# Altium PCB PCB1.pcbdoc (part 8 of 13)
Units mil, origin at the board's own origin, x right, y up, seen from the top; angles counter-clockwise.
Board outline 5895.51 x 5895.51 mil, 8 copper layers (Top Layer, L2_GND1, L3_SIG1, L4_GND2, L5_PWR, L6_SIG2, L7_GND3, Bottom Layer), stack 63.761 mil thick; 673 components, 558 nets, 2797 pads, 1861 vias.
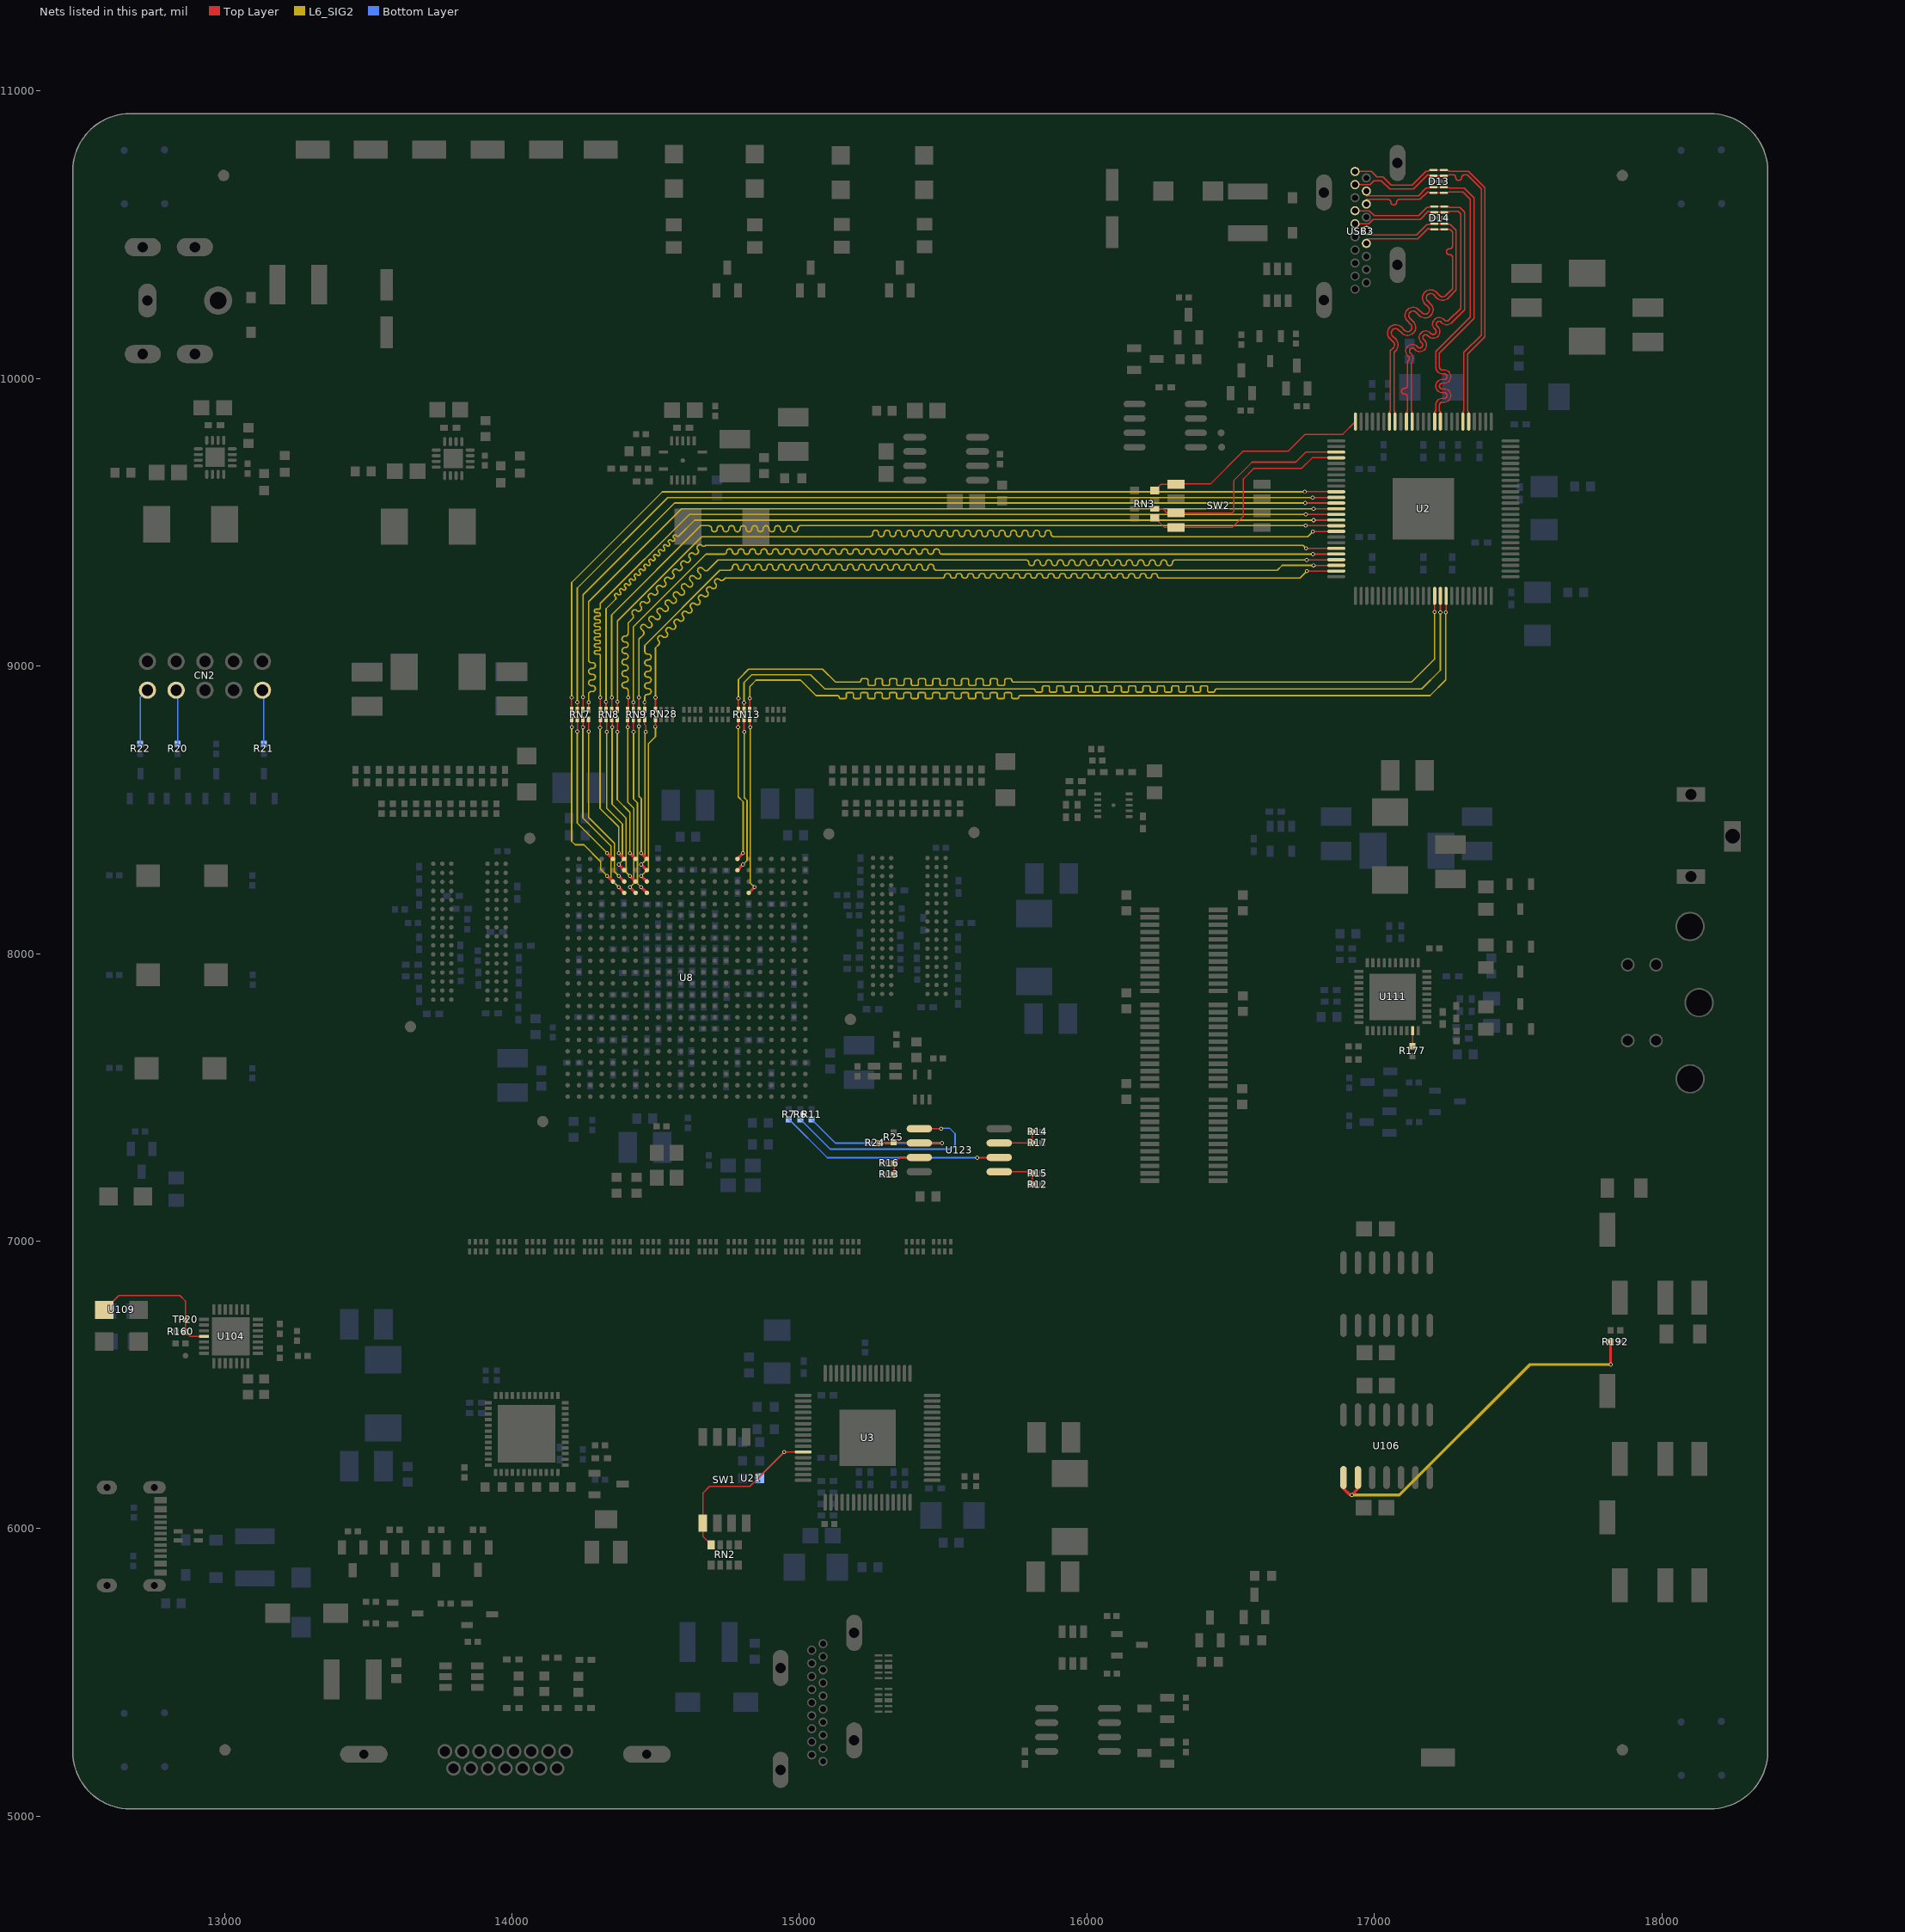
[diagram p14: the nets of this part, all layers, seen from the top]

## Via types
v1: diameter 23.62, hole 15.75, Top Layer to Bottom Layer, 621 vias
v2: diameter 13.8, hole 7.9, Top Layer to Bottom Layer, 567 vias
v3: diameter 13.78, hole 7.87, Top Layer to Bottom Layer, 529 vias
v4: diameter 13.78, hole 7.9, Top Layer to Bottom Layer, 114 vias
v5: diameter 15.75, hole 7.87, Top Layer to Bottom Layer, 16 vias
v6: diameter 24, hole 12, Top Layer to Bottom Layer, 10 vias
v7: diameter 11.81, hole 7.87, Top Layer to Bottom Layer, 4 vias

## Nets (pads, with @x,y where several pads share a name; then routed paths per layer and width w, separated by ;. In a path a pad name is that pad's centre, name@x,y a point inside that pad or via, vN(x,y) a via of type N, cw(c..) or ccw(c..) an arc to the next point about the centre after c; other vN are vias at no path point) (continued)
MIC2_OR: R192.1 U106.8 U106.9 | length 1314.7
  Top Layer w10: U106.8@16892.36,6177.98 16892.36,6140 16915.36,6117 v4(16921.36,6117) 16940.36,6136 16940.36,6175.98 U106.9@16942.36,6177.98 ; R192.1@17821.32,6650 17821.32,6572.04 v3(17822.36,6571)
  L6_SIG2 w10: v4(16921.36,6117) 17086.36,6117 17540.36,6571 v3(17822.36,6571)
  other v3: 17822.36,6571
MSEN: RN2.8 SW1.1 U3.11 U21.2 | length 725.3
  Top Layer w4.7: RN2.8@14693.12,5944.44 14664.36,5973.19 SW1.1@14664.36,6019 14664.36,6124 14687.36,6147 14827.36,6147 v4(14947.15,6266.79) U3.11@15012.95,6266.79
  Bottom Layer w4.7: U21.2@14862.02,6176 14862.02,6181.66 v4(14947.15,6266.79)
OCK_INV: RN3.8 SW2.1 U2.100 | length 797.5
  Top Layer w4.7: RN3.8@16236.01,9610.24 16257.77,9632 SW2.1@16309.36,9632 16310.36,9633 16429.36,9633 16543.36,9747 16700.36,9747 16759.36,9806 16889.99,9806 U2.100@16934.14,9850.15
PIXS: RN3.5 SW2.4 U2.4 | length 821.6
  Top Layer w4.7: RN3.5@16236.01,9515.76 16269.77,9482 SW2.4@16309.36,9482 16505.36,9482 16544.36,9521 16544.36,9651 16580.36,9687 16746.36,9687 16783.52,9724.16 U2.4@16867.21,9724.16
QSPI_CCLK: R11.1 R24.1 R25.2 U123.6 | length 705.8
  Top Layer w4.7: R24.1@15279.4,7341 15324.4,7341 R25.2@15327.36,7343.96 15330.06,7341.26 U123.6@15417.2,7341.26 15417.46,7341 v3(15495.36,7341)
  Bottom Layer w4.7: R11.1@15042.36,7423.96 15125.32,7341 v3(15495.36,7341)
QSPI_CS: R12.1 R15.1 U123.1 | length 156.3
  Top Layer w4.7: U123.1@15695.16,7241.26 15805.06,7241.26 R15.1@15810.32,7236 R12.1@15810.32,7197
QSPI_DIN: R7.1 U123.2 | length 787.8
  Top Layer w4.7: v3(15618.36,7290) 15693.91,7290 U123.2@15695.16,7291.26
  Bottom Layer w4.7: R7.1@14963.36,7423.96 15097.32,7290 v3(15618.36,7290)
QSPI_HOLD: R13.1 R16.1 U123.7 | length 135.2
  Top Layer w4.7: R13.1@15329.4,7232 R16.1@15329.4,7271 15349.65,7291.26 U123.7@15417.2,7291.26
QSPI_OUT: R6.1 U123.5 | length 759
  Top Layer w4.7: U123.5@15417.2,7391.26 15417.46,7391 v3(15493.36,7391)
  Bottom Layer w4.7: R6.1@15003.36,7423.96 15107.32,7320 15527.36,7320 15541.36,7334 15541.36,7374 15523.36,7392 15494.36,7392 v3(15493.36,7391)
QSPI_WP: R14.1 R17.1 U123.3 | length 154.1
  Top Layer w4.7: U123.3@15695.16,7341.26 R17.1@15810.06,7341.26 ; R17.1@15810.32,7341 R17.1@15810.06,7341.26 ; R14.1@15810.32,7380 15810.32,7341.51 R17.1@15810.06,7341.26
RXD: R160.1 TP20.1 U104.25 U109.1 | length 488.6
  Top Layer w4.7: U109.1@12582.62,6761 12632.62,6811 12845.36,6811 12864.07,6792.29 TP20.1@12864.07,6726.85 12864.73,6726.19 R160.1@12864.73,6684.8 12880.62,6668.91 U104.25@12929.09,6668.91
ST: RN3.6 SW2.3 U2.3 | length 788.5
  Top Layer w4.7: RN3.6@16236.01,9547.25 16264.11,9547.25 16279.36,9532 SW2.3@16309.36,9532 16505.36,9532 16510.36,9537 16510.36,9645 16574.36,9709 16726.36,9709 16761.21,9743.85 U2.3@16867.21,9743.85
SVIDEO_CLKIN_27M: R177.2 U111.19 | length 53.2
  Top Layer w4.7: R177.2@17132.36,7678.04 17132.56,7678.24 U111.19@17132.56,7731.16
TCK: CN2.1 R22.1 | length 197
  Bottom Layer w4.7: R22.1@12707.36,8729.37 12707.36,8891 CN2.1@12732.36,8916
TDI: CN2.9 R21.1 | length 188.7
  Bottom Layer w4.7: CN2.9@13132.36,8916 13137.36,8911 R21.1@13137.36,8729.37
TDO: CN2.3 R20.1 | length 188.7
  Bottom Layer w4.7: CN2.3@12832.36,8916 12837.36,8911 R20.1@12837.36,8729.37
TFP401_C+: D14.4 D14.7 U2.93 USB3.10 | length 1353.3
  Top Layer w4: USB3.10@16972.04,10515.22 16972.04,10500.38 16973.46,10498.97 17145.92,10498.97 17181.92,10534.97 17189.31,10534.97 17192.64,10538.3 D14.4@17208.03,10538.3 17240.13,10538.3 D14.7@17241.56,10536.87 ; U2.93@17071.93,9850.15 17071.93,9883.65 17068.59,9886.99 17068.59,10091.23 17074.38,10097.03 ccw(c17054.58,10116.83) 17074.38,10136.63 17062.95,10148.06 cw(c17073.56,10158.66) 17084.16,10169.27 17095.59,10157.84 ccw(c17115.39,10177.64) 17135.19,10197.44 17123.76,10208.87 cw(c17134.37,10219.47) 17144.97,10230.08 17156.4,10218.65 ccw(c17176.2,10238.45) 17196,10258.25 17184.57,10269.68 cw(c17195.18,10280.28) 17205.78,10290.89 17217.22,10279.46 ccw(c17237.01,10299.26) 17256.81,10279.46 17284.4,10307.05 17284.4,10515.28 17262.8,10536.89 17244.1,10536.89 D14.7@17242.69,10538.3
TFP401_C-: D14.5 D14.6 U2.94 USB3.12 | length 1351.7
  Top Layer w4: USB3.12@16972.04,10469.71 16972.04,10484.55 16973.46,10485.97 17151.31,10485.97 17187.31,10521.97 17189.31,10521.97 17192.64,10518.63 D14.5@17208.04,10518.63 17239.81,10518.63 D14.6@17240.41,10518.03 ; U2.94@17052.25,9850.15 17052.25,9883.65 17055.59,9886.99 17055.59,10096.62 17065.19,10106.22 ccw(c17054.58,10116.83) 17065.19,10127.43 17053.76,10138.86 cw(c17073.56,10158.66) 17093.35,10178.46 17104.79,10167.03 ccw(c17115.39,10177.64) 17126,10188.24 17114.57,10199.67 cw(c17134.37,10219.47) 17154.17,10239.27 17165.6,10227.84 ccw(c17176.2,10238.45) 17186.81,10249.06 17175.38,10260.49 cw(c17195.18,10280.28) 17214.98,10300.08 17226.41,10288.65 ccw(c17237.01,10299.26) 17247.62,10288.65 17271.4,10312.44 17271.4,10420.77 ccw(c17261.4,10420.77) 17261.4,10430.77 17260.79,10430.77 cw(c17260.79,10440.77) 17260.79,10450.77 17261.4,10450.77 ccw(c17261.4,10460.77) 17271.4,10460.77 17271.4,10509.9 17263.31,10517.99 17242.95,10517.99 17242.69,10518.26 D14.6@17242.69,10518.63
TFP401_CTL1: RN13.5 U2.40 | length 3206
  Top Layer w4.7: RN13.5@14787.83,8847.83 v3(14787.83,8887) ; U2.40@17208.87,9244.88 17209.36,9244.4 v4(17209.36,9188)
  L6_SIG2 w5: v3(14787.83,8887) 14787.83,8953.47 14823.46,8989.1 15080.67,8989.1 15125.71,8944.07 15207.93,8944.07 ccw(c15207.93,8950.08) 15213.94,8950.08 cw(c15219.95,8950.08) 15219.95,8956.09 15232.93,8956.09 cw(c15232.93,8950.08) 15238.94,8950.08 15238.94,8938.06 ccw(c15244.95,8938.06) 15244.95,8932.05 15257.93,8932.05 ccw(c15257.93,8938.06) 15263.94,8938.06 15263.94,8950.08 cw(c15269.95,8950.08) 15269.95,8956.09 15282.93,8956.09 cw(c15282.93,8950.08) 15288.94,8950.08 15288.94,8938.06 ccw(c15294.95,8938.06) 15294.95,8932.05 15307.93,8932.05 ccw(c15307.93,8938.06) 15313.94,8938.06 15313.94,8950.08 cw(c15319.95,8950.08) 15319.95,8956.09 15332.93,8956.09 cw(c15332.93,8950.08) 15338.94,8950.08 15338.94,8938.06 ccw(c15344.95,8938.06) 15344.95,8932.05 15357.93,8932.05 ccw(c15357.93,8938.06) 15363.94,8938.06 15363.94,8950.08 cw(c15369.95,8950.08) 15369.95,8956.09 15382.93,8956.09 cw(c15382.93,8950.08) 15388.94,8950.08 15388.94,8938.06 ccw(c15394.95,8938.06) 15394.95,8932.05 15407.93,8932.05 ccw(c15407.93,8938.06) 15413.94,8938.06 15413.94,8950.08 cw(c15419.95,8950.08) 15419.95,8956.09 15432.93,8956.09 cw(c15432.93,8950.08) 15438.94,8950.08 15438.94,8938.06 ccw(c15444.95,8938.06) 15444.95,8932.05 15457.93,8932.05 ccw(c15457.93,8938.06) 15463.94,8938.06 15463.94,8950.08 cw(c15469.95,8950.08) 15469.95,8956.09 15482.93,8956.09 cw(c15482.93,8950.08) 15488.94,8950.08 15488.94,8938.06 ccw(c15494.95,8938.06) 15494.95,8932.05 15507.93,8932.05 ccw(c15507.93,8938.06) 15513.94,8938.06 15513.94,8950.08 cw(c15519.95,8950.08) 15519.95,8956.09 15532.93,8956.09 cw(c15532.93,8950.08) 15538.94,8950.08 15538.94,8938.06 ccw(c15544.95,8938.06) 15544.95,8932.05 15557.93,8932.05 ccw(c15557.93,8938.06) 15563.94,8938.06 15563.94,8950.08 cw(c15569.95,8950.08) 15569.95,8956.09 15582.93,8956.09 cw(c15582.93,8950.08) 15588.94,8950.08 15588.94,8938.06 ccw(c15594.95,8938.06) 15594.95,8932.05 15607.93,8932.05 ccw(c15607.93,8938.06) 15613.94,8938.06 15613.94,8950.08 cw(c15619.95,8950.08) 15619.95,8956.09 15632.93,8956.09 cw(c15632.93,8950.08) 15638.94,8950.08 15638.94,8938.06 ccw(c15644.95,8938.06) 15644.95,8932.05 15657.93,8932.05 ccw(c15657.93,8938.06) 15663.94,8938.06 15663.94,8950.08 cw(c15669.95,8950.08) 15669.95,8956.09 15682.93,8956.09 cw(c15682.93,8950.08) 15688.94,8950.08 15688.94,8938.06 ccw(c15694.95,8938.06) 15694.95,8932.05 15707.93,8932.05 ccw(c15707.93,8938.06) 15713.94,8938.06 15713.94,8950.08 cw(c15719.95,8950.08) 15719.95,8956.09 15732.93,8956.09 cw(c15732.93,8950.08) 15738.94,8950.08 ccw(c15744.95,8950.08) 15744.95,8944.07 17128.96,8944.07 17209.62,9024.73 ; 17209.36,9024.73 v4(17209.36,9188)
TFP401_CTL1_FPGA: RN13.4 U8.A16 | length 500.7
  Top Layer w4.7: v3(14786.59,8786.88) 14787.83,8788.12 RN13.4@14787.83,8814.17
  Top Layer w10: U8.A16@14784.52,8329.4 v2(14804.2,8349.07)
  L6_SIG2 w5: v3(14786.59,8786.88) 14787.07,8786.41 14787.07,8545.09 14804.2,8527.96 v2(14804.2,8349.07)
TFP401_CTL2: RN13.6 U2.41 | length 3261.2
  Top Layer w4.7: v3(14807.36,8873) 14807.52,8872.84 RN13.6@14807.52,8847.83 ; v4(17229.36,9187) U2.41@17229.36,9243.95
  L6_SIG2 w5: v3(14807.36,8873) 14807.36,8943 14834.46,8970.1 15038.67,8970.1 15088.73,8920.04 15814.44,8920.04 cw(c15814.44,8914.55) 15819.93,8914.55 ccw(c15825.41,8914.55) 15825.41,8909.07 15839.44,8909.07 ccw(c15839.44,8914.55) 15844.93,8914.55 15844.93,8925.53 cw(c15850.41,8925.53) 15850.41,8931.01 15864.44,8931.01 cw(c15864.44,8925.53) 15869.93,8925.53 15869.93,8914.55 ccw(c15875.41,8914.55) 15875.41,8909.07 15889.44,8909.07 ccw(c15889.44,8914.55) 15894.93,8914.55 15894.93,8925.53 cw(c15900.41,8925.53) 15900.41,8931.01 15914.44,8931.01 cw(c15914.44,8925.53) 15919.93,8925.53 15919.93,8914.55 ccw(c15925.41,8914.55) 15925.41,8909.07 15939.44,8909.07 ccw(c15939.44,8914.55) 15944.93,8914.55 15944.93,8925.53 cw(c15950.41,8925.53) 15950.41,8931.01 15964.44,8931.01 cw(c15964.44,8925.53) 15969.93,8925.53 15969.93,8914.55 ccw(c15975.41,8914.55) 15975.41,8909.07 15989.44,8909.07 ccw(c15989.44,8914.55) 15994.93,8914.55 15994.93,8925.53 cw(c16000.41,8925.53) 16000.41,8931.01 16014.44,8931.01 cw(c16014.44,8925.53) 16019.93,8925.53 16019.93,8914.55 ccw(c16025.41,8914.55) 16025.41,8909.07 16039.44,8909.07 ccw(c16039.44,8914.55) 16044.93,8914.55 16044.93,8925.53 cw(c16050.41,8925.53) 16050.41,8931.01 16064.44,8931.01 cw(c16064.44,8925.53) 16069.93,8925.53 16069.93,8914.55 ccw(c16075.41,8914.55) 16075.41,8909.07 16089.44,8909.07 ccw(c16089.44,8914.55) 16094.93,8914.55 16094.93,8925.53 cw(c16100.41,8925.53) 16100.41,8931.01 16114.44,8931.01 cw(c16114.44,8925.53) 16119.93,8925.53 16119.93,8914.55 ccw(c16125.41,8914.55) 16125.41,8909.07 16139.44,8909.07 ccw(c16139.44,8914.55) 16144.93,8914.55 16144.93,8925.53 cw(c16150.41,8925.53) 16150.41,8931.01 16164.44,8931.01 cw(c16164.44,8925.53) 16169.93,8925.53 16169.93,8914.55 ccw(c16175.41,8914.55) 16175.41,8909.07 16189.44,8909.07 ccw(c16189.44,8914.55) 16194.93,8914.55 16194.93,8925.53 cw(c16200.41,8925.53) 16200.41,8931.01 16214.44,8931.01 cw(c16214.44,8925.53) 16219.93,8925.53 16219.93,8914.55 ccw(c16225.41,8914.55) 16225.41,8909.07 16239.44,8909.07 ccw(c16239.44,8914.55) 16244.93,8914.55 16244.93,8925.53 cw(c16250.41,8925.53) 16250.41,8931.01 16264.44,8931.01 cw(c16264.44,8925.53) 16269.93,8925.53 16269.93,8914.55 ccw(c16275.41,8914.55) 16275.41,8909.07 16289.44,8909.07 ccw(c16289.44,8914.55) 16294.93,8914.55 16294.93,8925.53 cw(c16300.41,8925.53) 16300.41,8931.01 16314.44,8931.01 cw(c16314.44,8925.53) 16319.93,8925.53 16319.93,8914.55 ccw(c16325.41,8914.55) 16325.41,8909.07 16339.44,8909.07 ccw(c16339.44,8914.55) 16344.93,8914.55 16344.93,8925.53 cw(c16350.41,8925.53) 16350.41,8931.01 16364.44,8931.01 cw(c16364.44,8925.53) 16369.93,8925.53 16369.93,8914.55 ccw(c16375.41,8914.55) 16375.41,8909.07 16389.44,8909.07 ccw(c16389.44,8914.55) 16394.93,8914.55 16394.93,8925.53 cw(c16400.41,8925.53) 16400.41,8931.01 16414.44,8931.01 cw(c16414.44,8925.53) 16419.93,8925.53 16419.93,8914.55 ccw(c16425.41,8914.55) 16425.41,8909.07 16439.44,8909.07 ccw(c16439.44,8914.55) 16444.93,8914.55 cw(c16450.41,8914.55) 16450.41,8920.04 17164.13,8920.04 17229.43,8985.34 ; 17229.36,8985.34 v4(17229.36,9187)
TFP401_CTL2_FPGA: RN13.3 U8.B16 | length 542.4
  Top Layer w4.7: RN13.3@14807.52,8814.17 14807.52,8770.96 v3(14807.8,8770.68)
  Top Layer w10: U8.B16@14784.52,8290.01 v2(14804.2,8309.69)
  L6_SIG2 w5: v2(14804.2,8309.69) 14818.07,8323.56 14818.07,8532.25 14807.8,8542.51 v3(14807.8,8770.68)
TFP401_CTL3: RN13.7 U2.42 | length 3247
  Top Layer w4.7: RN13.7@14827.2,8847.83 v3(14827.2,8887) ; v4(17248.36,9186) 17249.34,9186.98 U2.42@17249.34,9237
  L6_SIG2 w5: v3(14827.2,8887) 14827.2,8928.84 14849.46,8951.1 15003.81,8951.1 15057.72,8897.19 15132.84,8897.19 cw(c15132.84,8891.97) 15138.05,8891.97 ccw(c15143.27,8891.97) 15143.27,8886.76 15157.84,8886.76 ccw(c15157.84,8891.97) 15163.05,8891.97 15163.05,8902.41 cw(c15168.27,8902.41) 15168.27,8907.62 15182.84,8907.62 cw(c15182.84,8902.41) 15188.05,8902.41 15188.05,8891.97 ccw(c15193.27,8891.97) 15193.27,8886.76 15207.84,8886.76 ccw(c15207.84,8891.97) 15213.05,8891.97 15213.05,8902.41 cw(c15218.27,8902.41) 15218.27,8907.62 15232.84,8907.62 cw(c15232.84,8902.41) 15238.05,8902.41 15238.05,8891.97 ccw(c15243.27,8891.97) 15243.27,8886.76 15257.84,8886.76 ccw(c15257.84,8891.97) 15263.05,8891.97 15263.05,8902.41 cw(c15268.27,8902.41) 15268.27,8907.62 15282.84,8907.62 cw(c15282.84,8902.41) 15288.05,8902.41 15288.05,8891.97 ccw(c15293.27,8891.97) 15293.27,8886.76 15307.84,8886.76 ccw(c15307.84,8891.97) 15313.05,8891.97 15313.05,8902.41 cw(c15318.27,8902.41) 15318.27,8907.62 15332.84,8907.62 cw(c15332.84,8902.41) 15338.05,8902.41 15338.05,8891.97 ccw(c15343.27,8891.97) 15343.27,8886.76 15357.84,8886.76 ccw(c15357.84,8891.97) 15363.05,8891.97 15363.05,8902.41 cw(c15368.27,8902.41) 15368.27,8907.62 15382.84,8907.62 cw(c15382.84,8902.41) 15388.05,8902.41 15388.05,8891.97 ccw(c15393.27,8891.97) 15393.27,8886.76 15407.84,8886.76 ccw(c15407.84,8891.97) 15413.05,8891.97 15413.05,8902.41 cw(c15418.27,8902.41) 15418.27,8907.62 15432.84,8907.62 cw(c15432.84,8902.41) 15438.05,8902.41 15438.05,8891.97 ccw(c15443.27,8891.97) 15443.27,8886.76 15457.84,8886.76 ccw(c15457.84,8891.97) 15463.05,8891.97 15463.05,8902.41 cw(c15468.27,8902.41) 15468.27,8907.62 15482.84,8907.62 cw(c15482.84,8902.41) 15488.05,8902.41 15488.05,8891.97 ccw(c15493.27,8891.97) 15493.27,8886.76 15507.84,8886.76 ccw(c15507.84,8891.97) 15513.05,8891.97 15513.05,8902.41 cw(c15518.27,8902.41) 15518.27,8907.62 15532.84,8907.62 cw(c15532.84,8902.41) 15538.05,8902.41 15538.05,8891.97 ccw(c15543.27,8891.97) 15543.27,8886.76 15557.84,8886.76 ccw(c15557.84,8891.97) 15563.05,8891.97 15563.05,8902.41 cw(c15568.27,8902.41) 15568.27,8907.62 15582.84,8907.62 cw(c15582.84,8902.41) 15588.05,8902.41 15588.05,8891.97 ccw(c15593.27,8891.97) 15593.27,8886.76 15607.84,8886.76 ccw(c15607.84,8891.97) 15613.05,8891.97 15613.05,8902.41 cw(c15618.27,8902.41) 15618.27,8907.62 15632.84,8907.62 cw(c15632.84,8902.41) 15638.05,8902.41 15638.05,8891.97 ccw(c15643.27,8891.97) 15643.27,8886.76 15657.84,8886.76 ccw(c15657.84,8891.97) 15663.05,8891.97 15663.05,8902.41 cw(c15668.27,8902.41) 15668.27,8907.62 15682.84,8907.62 cw(c15682.84,8902.41) 15688.05,8902.41 15688.05,8891.97 ccw(c15693.27,8891.97) 15693.27,8886.76 15707.84,8886.76 ccw(c15707.84,8891.97) 15713.05,8891.97 15713.05,8902.41 cw(c15718.27,8902.41) 15718.27,8907.62 15732.84,8907.62 cw(c15732.84,8902.41) 15738.05,8902.41 15738.05,8891.97 ccw(c15743.27,8891.97) 15743.27,8886.76 15757.84,8886.76 ccw(c15757.84,8891.97) 15763.05,8891.97 cw(c15768.27,8891.97) 15768.27,8897.19 17193.49,8897.19 17248.24,8951.95 17248.24,9185.88 v4(17248.36,9186)
TFP401_CTL3_FPGA: RN13.2 U8.D17 | length 617.8
  Top Layer w4.7: RN13.2@14827.2,8814.17 14827.2,8788.29 v3(14828.66,8786.83)
  Top Layer w10: U8.D17@14823.89,8211.27 v2(14843.57,8230.95)
  L6_SIG2 w5: v3(14828.66,8786.83) 14828.96,8786.52 14828.96,8245.56 v2(14843.57,8230.95)
TFP401_D0: RN7.5 U2.10 | length 3211.2
  Top Layer w4.7: RN7.5@14207.83,8847.83 v3(14207.83,8891) ; v4(16757.36,9606) 16845.25,9606 U2.10@16845.58,9605.68
  L6_SIG2 w5: v3(14207.83,8891) 14207.83,9290.47 14523.36,9606 v4(16757.36,9606)
TFP401_D0+: D14.1 D14.10 U2.90 USB3.7 | length 1351.8
  Top Layer w4: USB3.7@16931.24,10582.41 16931.96,10583.13 16982.45,10583.13 16999.51,10566.07 17153.96,10566.07 17181.92,10594.03 17189.31,10594.03 17192.64,10597.37 D14.1@17208.03,10597.37 17240.82,10597.37 D14.10@17241.02,10597.17 ; U2.90@17130.99,9850.15 17130.99,9883.65 17127.64,9886.99 17127.64,10053.21 ccw(c17111.38,10069.47) 17127.64,10085.73 17124.8,10088.58 cw(c17131.87,10095.65) 17138.94,10102.72 17141.78,10099.88 ccw(c17158.05,10116.14) 17174.31,10132.4 17171.47,10135.25 cw(c17178.54,10142.32) 17185.61,10149.39 17188.45,10146.54 ccw(c17204.72,10162.81) 17220.98,10179.07 17218.14,10181.92 cw(c17225.21,10188.99) 17232.28,10196.06 17235.12,10193.21 ccw(c17251.39,10209.48) 17267.65,10193.21 17313.18,10238.74 17313.18,10577.77 17296.91,10594.03 17261.41,10594.03 17258.07,10597.37 D14.10@17242.69,10597.37
TFP401_D0-: D14.2 D14.9 U2.91 USB3.9 | length 1350
  Top Layer w4: USB3.9@16932.97,10537.68 16980.06,10537.68 16995.45,10553.07 17159.34,10553.07 17187.31,10581.03 17189.31,10581.03 17192.64,10577.7 D14.2@17208.03,10577.7 D14.9@17242.69,10577.7 ; U2.91@17111.3,9850.15 17111.3,9883.65 17114.64,9886.99 17114.64,9935.67 ccw(c17104.64,9935.67) 17104.64,9945.67 17104.23,9945.67 cw(c17104.23,9955.67) 17104.23,9965.67 17104.64,9965.67 ccw(c17104.64,9975.67) 17114.64,9975.67 17114.64,10058.59 17118.45,10062.4 ccw(c17111.38,10069.47) 17118.45,10076.54 17115.61,10079.38 cw(c17131.87,10095.65) 17148.13,10111.91 17150.98,10109.07 ccw(c17158.05,10116.14) 17165.12,10123.21 17162.28,10126.05 cw(c17178.54,10142.32) 17194.8,10158.58 17197.65,10155.74 ccw(c17204.72,10162.81) 17211.79,10169.88 17208.94,10172.72 cw(c17225.21,10188.99) 17241.47,10205.25 17244.31,10202.41 ccw(c17251.39,10209.48) 17258.46,10202.41 17300.18,10244.12 17300.18,10572.39 17291.53,10581.03 17261.41,10581.03 17258.07,10577.7 17246.14,10577.7 D14.9@17246.63,10578.19
TFP401_D0_FPGA: RN7.4 U8.C5 | length 641.5
  Top Layer w4.7: RN7.4@14206.97,8814.02 14208.37,8812.61 v3(14208.37,8787.11)
  Top Layer w10: v2(14331.79,8270.32) U8.C5@14351.46,8250.65
  L6_SIG2 w5: v3(14208.37,8787.11) 14207.88,8786.62 14207.88,8390.55 14220.24,8378.19 14250.75,8378.19 14309.07,8319.87 14309.07,8293.04 v2(14331.79,8270.32)
TFP401_D1: RN7.6 U2.11 | length 3189.7
  Top Layer w4.7: RN7.6@14227.52,8847.83 v3(14227.52,8874) ; v4(16785.36,9586) 16863.13,9586 U2.11@16863.37,9586.25
  L6_SIG2 w5: v3(14227.52,8874) 14227.52,9271.16 14542.36,9586 v4(16785.36,9586)
TFP401_D1+: D13.4 D13.7 U2.85 USB3.4 | length 1350.1
  Top Layer w4: USB3.4@16972.04,10651.75 16972.04,10636.91 16973.46,10635.5 17153.46,10635.5 17179.92,10661.97 17187.31,10661.97 17190.64,10665.3 D13.4@17206.03,10665.3 D13.7@17240.69,10665.3 D13.7@17241.78,10666.42 ; U2.85@17229.41,9850.15 17229.41,9883.65 17226.07,9886.99 17226.07,9907.61 cw(c17236.07,9907.61) 17236.07,9917.61 17242.58,9917.61 ccw(c17242.58,9940.61) 17242.58,9963.61 17236.07,9963.61 cw(c17236.07,9973.61) 17236.07,9983.61 17242.58,9983.61 ccw(c17242.58,10006.61) 17242.58,10029.61 17236.07,10029.61 cw(c17236.07,10039.61) 17226.07,10039.61 17226.07,10088.17 17346.79,10208.89 17346.79,10628 17312.82,10661.97 17259.41,10661.97 17256.07,10665.3 D13.7@17240.69,10665.3
TFP401_D1-: D13.5 D13.6 U2.86 USB3.6 | length 1348.9
  Top Layer w4: USB3.6@16972.04,10606.24 16972.04,10621.09 16973.46,10622.5 17047.48,10622.5 cw(c17047.48,10612.92) 17057.06,10612.92 ccw(c17066.64,10612.92) 17066.64,10603.33 17067.48,10603.33 ccw(c17067.48,10612.92) 17077.06,10612.92 cw(c17086.64,10612.92) 17086.64,10622.5 17158.84,10622.5 17185.31,10648.97 17187.31,10648.97 17190.64,10645.63 D13.5@17206.04,10645.63 D13.6@17240.69,10645.63 17256.07,10645.63 17259.41,10648.97 17307.44,10648.97 17333.79,10622.62 17333.79,10214.28 17213.07,10093.56 17213.07,10039.61 ccw(c17236.07,10039.61) 17236.07,10016.61 17242.58,10016.61 cw(c17242.58,10006.61) 17242.58,9996.61 17236.07,9996.61 ccw(c17236.07,9973.61) 17236.07,9950.61 17242.58,9950.61 cw(c17242.58,9940.61) 17242.58,9930.61 17236.07,9930.61 ccw(c17236.07,9907.61) 17213.07,9907.61 17213.07,9886.99 17209.73,9883.65 U2.86@17209.73,9850.15
TFP401_D1_FPGA: RN7.3 U8.A5 | length 536.3
  Top Layer w4.7: v3(14227.24,8772.21) 14227.52,8772.49 RN7.3@14227.52,8814.17
  Top Layer w10: v2(14331.79,8349.07) U8.A5@14351.46,8329.4
  L6_SIG2 w5: v3(14227.24,8772.21) 14227.24,8453.62 v2(14331.79,8349.07)
TFP401_D2: RN7.7 U2.12 | length 3154.2
  Top Layer w4.7: RN7.7@14247.2,8847.83 v3(14247.2,8892) ; v4(16759.36,9567) 16867.61,9567 U2.12@16868.73,9565.89
  L6_SIG2 w5: v3(14247.2,8892) 14247.2,9247.84 14566.36,9567 v4(16759.36,9567)
TFP401_D2+: D13.1 D13.10 U2.80 USB3.1 | length 1357.1
  Top Layer w4: USB3.1@16933.42,10720.56 16934.19,10719.8 16989.98,10719.8 17008.97,10700.81 17029.84,10700.81 17058.64,10672.01 17130.89,10672.01 17179.92,10721.03 17187.31,10721.03 17190.64,10724.37 D13.1@17206.03,10724.37 17238.45,10724.37 D13.10@17239.19,10725.11 ; D13.10@17240.69,10724.37 17256.07,10724.37 17259.41,10721.03 17327.64,10721.03 17384.76,10663.91 17384.76,10145.5 17324.49,10085.23 17324.49,9886.99 17327.84,9883.65 U2.80@17327.84,9850.15
TFP401_D2-: D13.2 D13.9 U2.81 USB3.3 | length 1357.3
  Top Layer w4: USB3.3@16931.62,10674.11 16984.48,10674.11 16998.18,10687.81 17024.45,10687.81 17053.25,10659.01 17136.28,10659.01 17185.31,10708.03 17187.31,10708.03 17190.64,10704.7 D13.2@17206.03,10704.7 17238.02,10704.7 D13.9@17239.19,10703.53 ; D13.9@17240.69,10704.7 17256.07,10704.7 17259.41,10708.03 17273.37,10708.03 cw(c17273.37,10698.3) 17283.1,10698.3 ccw(c17292.83,10698.3) 17292.83,10688.57 17293.37,10688.57 ccw(c17293.37,10698.3) 17303.1,10698.3 cw(c17312.83,10698.3) 17312.83,10708.03 17322.25,10708.03 17371.76,10658.52 17371.76,10150.89 17311.49,10090.61 17311.49,9886.99 17308.15,9883.65 U2.81@17308.15,9850.15
TFP401_D2_FPGA: RN7.2 U8.D6 | length 662.6
  Top Layer w4.7: v3(14246.99,8787.52) 14247.2,8787.73 RN7.2@14247.2,8814.17
  Top Layer w10: v2(14371.15,8230.95) U8.D6@14390.82,8211.27
  L6_SIG2 w5: v3(14246.99,8787.52) 14246.99,8471.75 14344.64,8374.11 14344.64,8257.46 v2(14371.15,8230.95)
TFP401_D3: RN7.8 U2.13 | length 3195.6
  Top Layer w4.7: RN7.8@14266.89,8847.83 v3(14266.89,8874) ; v4(16788.36,9547) 16861.99,9547 U2.13@16863.02,9545.97
  L6_SIG2 w5: v3(14266.89,8874) 14266.89,8901.53 cw(c14276.89,8901.53) 14276.89,8911.53 14280.36,8911.53 ccw(c14280.36,8921.53) 14280.36,8931.53 14276.89,8931.53 cw(c14276.89,8941.53) 14276.89,8951.53 14280.36,8951.53 ccw(c14280.36,8961.53) 14280.36,8971.53 14276.89,8971.53 cw(c14276.89,8981.53) 14276.89,8991.53 14280.36,8991.53 ccw(c14280.36,9001.53) 14280.36,9011.53 14276.89,9011.53 cw(c14276.89,9021.53) 14266.89,9021.53 14266.89,9223.53 14590.36,9547 v4(16788.36,9547)
TFP401_D3_FPGA: RN7.1 U8.C6 | length 614.9
  Top Layer w4.7: RN7.1@14266.89,8814.17 14267.47,8813.59 v3(14267.47,8772.09)
  Top Layer w10: v2(14371.15,8270.32) U8.C6@14390.82,8250.65
  L6_SIG2 w5: v3(14267.47,8772.09) 14267.47,8472.89 14356.36,8384 14356.36,8285.11 v2(14371.15,8270.32)
TFP401_D4: RN8.5 U2.14 | length 3280.5
  Top Layer w4.7: RN8.5@14307.83,8847.83 v3(14307.83,8891) ; v4(16761.36,9527) 16866.98,9527 U2.14@16867.26,9526.72
  L6_SIG2 w5: v3(14307.83,8891) 14307.83,9035.52 ccw(c14301.83,9035.52) 14301.83,9041.52 14292.74,9041.52 cw(c14292.74,9047.52) 14292.74,9053.52 14301.83,9053.52 ccw(c14301.83,9059.52) 14301.83,9065.52 14292.74,9065.52 cw(c14292.74,9071.52) 14292.74,9077.52 14301.83,9077.52 ccw(c14301.83,9083.52) 14301.83,9089.52 14292.74,9089.52 cw(c14292.74,9095.52) 14292.74,9101.52 14301.83,9101.52 ccw(c14301.83,9107.52) 14301.83,9113.52 14292.74,9113.52 cw(c14292.74,9119.52) 14292.74,9125.52 14301.83,9125.52 ccw(c14301.83,9131.52) 14301.83,9137.52 14292.74,9137.52 cw(c14292.74,9143.52) 14292.74,9149.52 14301.83,9149.52 ccw(c14301.83,9155.52) 14301.83,9161.52 14292.74,9161.52 cw(c14292.74,9167.52) 14292.74,9173.52 14301.83,9173.52 ccw(c14301.83,9179.52) 14301.83,9185.52 14292.74,9185.52 cw(c14292.74,9191.52) 14292.74,9197.52 14301.83,9197.52 ccw(c14301.83,9203.52) 14307.83,9203.52 14307.83,9217.47 14617.36,9527 v4(16761.36,9527)
TFP401_D4_FPGA: RN8.4 U8.A6 | length 520.1
  Top Layer w4.7: v3(14306.69,8785.99) 14307.83,8787.13 RN8.4@14307.83,8814.17
  Top Layer w10: v2(14371.15,8349.07) U8.A6@14390.82,8329.4
  L6_SIG2 w5: v3(14306.69,8785.99) 14306.69,8504.67 14371.15,8440.21 v2(14371.15,8349.07)
TFP401_D5: RN8.6 U2.15 | length 3257.9
  Top Layer w4.7: v3(14327.36,8875) 14327.52,8874.84 RN8.6@14327.52,8847.83 ; v4(16788.36,9507) 16788.52,9507.17 U2.15@16872.57,9507.17
  L6_SIG2 w5: v3(14327.36,8875) 14327.36,9199 14360.49,9232.13 ccw(c14356.24,9236.37) 14360.49,9240.62 14358.97,9242.13 cw(c14363.22,9246.37) 14367.46,9250.62 14368.97,9249.1 ccw(c14373.22,9253.34) 14377.46,9257.59 14375.94,9259.1 cw(c14380.19,9263.34) 14384.43,9267.59 14385.94,9266.07 ccw(c14390.19,9270.31) 14394.43,9274.56 14392.91,9276.07 cw(c14397.16,9280.31) 14401.4,9284.56 14402.91,9283.04 ccw(c14407.16,9287.28) 14411.4,9291.53 14409.88,9293.04 cw(c14414.13,9297.28) 14418.37,9301.53 14419.88,9300.01 ccw(c14424.13,9304.25) 14428.37,9308.5 14426.85,9310.01 cw(c14431.1,9314.25) 14435.34,9318.5 14436.85,9316.98 ccw(c14441.1,9321.23) 14445.34,9325.47 14443.83,9326.98 cw(c14448.07,9331.23) 14452.31,9335.47 14453.83,9333.95 ccw(c14458.07,9338.2) 14462.31,9342.44 14460.8,9343.95 cw(c14465.04,9348.2) 14469.28,9352.44 14470.8,9350.92 ccw(c14475.04,9355.17) 14479.28,9359.41 14477.77,9360.92 cw(c14482.01,9365.17) 14486.25,9369.41 14487.77,9367.89 ccw(c14492.01,9372.14) 14496.25,9376.38 14494.74,9377.89 cw(c14498.98,9382.14) 14503.22,9386.38 14504.74,9384.86 ccw(c14508.98,9389.11) 14513.22,9393.35 14511.71,9394.86 cw(c14515.95,9399.11) 14520.19,9403.35 14521.71,9401.84 ccw(c14525.95,9406.08) 14530.19,9410.32 14528.68,9411.84 cw(c14532.92,9416.08) 14537.16,9420.32 14538.68,9418.81 ccw(c14542.92,9423.05) 14547.16,9427.29 14545.65,9428.81 cw(c14549.89,9433.05) 14554.13,9437.29 14555.65,9435.78 ccw(c14559.89,9440.02) 14564.13,9444.26 14562.62,9445.78 cw(c14566.86,9450.02) 14571.1,9454.26 14572.62,9452.75 ccw(c14576.86,9456.99) 14581.1,9452.75 14635.36,9507 v4(16788.36,9507)
TFP401_D5_FPGA: RN8.3 U8.B6 | length 561.3
  Top Layer w4.7: RN8.3@14327.52,8814.17 14329.25,8812.44 v3(14329.25,8771.05)
  Top Layer w10: v2(14371.15,8309.69) U8.B6@14390.82,8290.01
  L6_SIG2 w5: v3(14329.25,8771.05) 14329.49,8770.81 14329.49,8505.34 14384.35,8450.48 14384.35,8322.89 v2(14371.15,8309.69)
TFP401_D6: RN8.7 U2.16 | length 3180.7
  Top Layer w4.7: RN8.7@14347.2,8847.83 v3(14347.2,8891) ; v4(16760.36,9488) 16868.7,9488 U2.16@16870.14,9486.55
  L6_SIG2 w5: v3(14347.2,8891) 14347.2,9177.84 14657.36,9488 14684.26,9488 cw(c14684.26,9478) 14694.26,9478 14694.26,9477 ccw(c14704.26,9477) 14714.26,9477 14714.26,9478 cw(c14724.26,9478) 14734.26,9478 14734.26,9477 ccw(c14744.26,9477) 14754.26,9477 14754.26,9478 cw(c14764.26,9478) 14774.26,9478 14774.26,9477 ccw(c14784.26,9477) 14794.26,9477 14794.26,9478 cw(c14804.26,9478) 14814.26,9478 14814.26,9477 ccw(c14824.26,9477) 14834.26,9477 14834.26,9478 cw(c14844.26,9478) 14854.26,9478 14854.26,9477 ccw(c14864.26,9477) 14874.26,9477 14874.26,9478 cw(c14884.26,9478) 14894.26,9478 14894.26,9477 ccw(c14904.26,9477) 14914.26,9477 14914.26,9478 cw(c14924.26,9478) 14934.26,9478 14934.26,9477 ccw(c14944.26,9477) 14954.26,9477 14954.26,9478 cw(c14964.26,9478) 14974.26,9478 14974.26,9477 ccw(c14984.26,9477) 14994.26,9477 14994.26,9478 cw(c15004.26,9478) 15004.26,9488 v4(16760.36,9488)
TFP401_D6_FPGA: RN8.2 U8.C7 | length 598.4
  Top Layer w4.7: RN8.2@14347.2,8814.17 14348.86,8812.51 v3(14348.86,8787.11)
  Top Layer w10: v2(14410.52,8270.32) U8.C7@14430.19,8250.65
  L6_SIG2 w5: v3(14348.86,8787.11) 14348.25,8786.51 14348.25,8520.05 14397.03,8471.27 14397.03,8283.8 v2(14410.52,8270.32)
TFP401_D7: RN8.8 U2.17 | length 3368.9
  Top Layer w4.7: RN8.8@14366.89,8847.83 v3(14366.89,8875) ; v4(16786.36,9468) 16868.39,9468 U2.17@16868.63,9467.76
  L6_SIG2 w5: v3(14366.89,8875) 14366.89,9156.53 14660.36,9450 15244.91,9450 ccw(c15244.91,9460) 15254.91,9460 15254.91,9462 cw(c15264.91,9462) 15274.91,9462 15274.91,9460 ccw(c15284.91,9460) 15294.91,9460 15294.91,9462 cw(c15304.91,9462) 15314.91,9462 15314.91,9460 ccw(c15324.91,9460) 15334.91,9460 15334.91,9462 cw(c15344.91,9462) 15354.91,9462 15354.91,9460 ccw(c15364.91,9460) 15374.91,9460 15374.91,9462 cw(c15384.91,9462) 15394.91,9462 15394.91,9460 ccw(c15404.91,9460) 15414.91,9460 15414.91,9462 cw(c15424.91,9462) 15434.91,9462 15434.91,9460 ccw(c15444.91,9460) 15454.91,9460 15454.91,9462 cw(c15464.91,9462) 15474.91,9462 15474.91,9460 ccw(c15484.91,9460) 15494.91,9460 15494.91,9462 cw(c15504.91,9462) 15514.91,9462 15514.91,9460 ccw(c15524.91,9460) 15534.91,9460 15534.91,9462 cw(c15544.91,9462) 15554.91,9462 15554.91,9460 ccw(c15564.91,9460) 15574.91,9460 15574.91,9462 cw(c15584.91,9462) 15594.91,9462 15594.91,9460 ccw(c15604.91,9460) 15614.91,9460 15614.91,9462 cw(c15624.91,9462) 15634.91,9462 15634.91,9460 ccw(c15644.91,9460) 15654.91,9460 15654.91,9462 cw(c15664.91,9462) 15674.91,9462 15674.91,9460 ccw(c15684.91,9460) 15694.91,9460 15694.91,9462 cw(c15704.91,9462) 15714.91,9462 15714.91,9460 ccw(c15724.91,9460) 15734.91,9460 15734.91,9462 cw(c15744.91,9462) 15754.91,9462 15754.91,9460 ccw(c15764.91,9460) 15774.91,9460 15774.91,9462 cw(c15784.91,9462) 15794.91,9462 15794.91,9460 ccw(c15804.91,9460) 15814.91,9460 15814.91,9462 cw(c15824.91,9462) 15834.91,9462 15834.91,9460 ccw(c15844.91,9460) 15854.91,9460 15854.91,9462 cw(c15864.91,9462) 15874.91,9462 15874.91,9460 ccw(c15884.91,9460) 15884.91,9450 16768.36,9450 v4(16786.36,9468)
TFP401_D7_FPGA: RN8.1 U8.A7 | length 511.4
  Top Layer w4.7: v3(14366.76,8770.42) 14366.89,8770.55 RN8.1@14366.89,8814.17
  Top Layer w10: v2(14410.52,8349.07) U8.A7@14430.19,8329.4
  L6_SIG2 w5: v3(14366.76,8770.42) 14366.46,8770.12 14366.46,8535.27 14410.52,8491.21 v2(14410.52,8349.07)
TFP401_D8: RN9.5 U2.20 | length 3204.8
  Top Layer w4.7: RN9.5@14402.83,8847.83 14404.36,8849.36 v3(14404.36,8891) ; v4(16762.36,9409) U2.20@16872.33,9409
  L6_SIG2 w5: v3(14404.36,8891) 14404.36,8913.79 ccw(c14394.36,8913.79) 14394.36,8923.79 14392.9,8923.79 cw(c14392.9,8933.79) 14392.9,8943.79 14394.36,8943.79 ccw(c14394.36,8953.79) 14394.36,8963.79 14392.9,8963.79 cw(c14392.9,8973.79) 14392.9,8983.79 14394.36,8983.79 ccw(c14394.36,8993.79) 14394.36,9003.79 14392.9,9003.79 cw(c14392.9,9013.79) 14392.9,9023.79 14394.36,9023.79 ccw(c14394.36,9033.79) 14394.36,9043.79 14392.9,9043.79 cw(c14392.9,9053.79) 14392.9,9063.79 14394.36,9063.79 ccw(c14394.36,9073.79) 14394.36,9083.79 14392.9,9083.79 cw(c14392.9,9093.79) 14392.9,9103.79 14394.36,9103.79 ccw(c14394.36,9113.79) 14404.36,9113.79 14404.36,9150 14420.24,9165.88 ccw(c14413.74,9172.38) 14420.24,9178.88 cw(c14426.74,9185.38) 14420.24,9191.88 14421.38,9193.03 cw(c14427.88,9186.53) 14434.38,9193.03 ccw(c14440.88,9199.53) 14447.38,9193.03 14448.53,9194.17 ccw(c14442.03,9200.67) 14448.53,9207.17 cw(c14455.03,9213.67) 14448.53,9220.17 14449.67,9221.31 cw(c14456.17,9214.81) 14462.67,9221.31 ccw(c14469.17,9227.81) 14475.67,9221.31 14476.81,9222.45 ccw(c14470.31,9228.95) 14476.81,9235.45 cw(c14483.31,9241.95) 14476.81,9248.45 14477.95,9249.59 cw(c14484.45,9243.09) 14490.95,9249.59 ccw(c14497.45,9256.09) 14503.95,9249.59 14505.09,9250.74 ccw(c14498.59,9257.24) 14505.09,9263.74 cw(c14511.59,9270.24) 14505.09,9276.74 14506.24,9277.88 cw(c14512.74,9271.38) 14519.24,9277.88 ccw(c14525.74,9284.38) 14532.24,9277.88 14533.38,9279.02 ccw(c14526.88,9285.52) 14533.38,9292.02 cw(c14539.88,9298.52) 14533.38,9305.02 14534.52,9306.16 cw(c14541.02,9299.66) 14547.52,9306.16 ccw(c14554.02,9312.66) 14560.52,9306.16 14561.66,9307.31 ccw(c14555.16,9313.81) 14561.66,9320.31 cw(c14568.16,9326.81) 14561.66,9333.31 14562.81,9334.45 cw(c14569.31,9327.95) 14575.81,9334.45 ccw(c14582.31,9340.95) 14588.81,9334.45 14589.95,9335.59 ccw(c14583.45,9342.09) 14589.95,9348.59 cw(c14596.45,9355.09) 14589.95,9361.59 14591.09,9362.73 cw(c14597.59,9356.23) 14604.09,9362.73 ccw(c14610.59,9369.23) 14617.09,9362.73 14618.23,9363.87 ccw(c14611.73,9370.37) 14618.23,9376.87 cw(c14624.73,9383.37) 14618.23,9389.87 14619.37,9391.02 cw(c14625.87,9384.52) 14632.37,9391.02 ccw(c14638.87,9397.52) 14645.37,9391.02 14646.52,9392.16 ccw(c14640.02,9398.66) 14646.52,9405.16 cw(c14653.02,9411.66) 14646.52,9418.16 14647.66,9419.3 cw(c14654.16,9412.8) 14660.66,9419.3 ccw(c14667.16,9425.8) 14673.66,9419.3 14674.36,9420 16751.36,9420 v4(16762.36,9409)
TFP401_D8_FPGA: RN9.4 U8.D7 | length 625
  Top Layer w4.7: v3(14402.74,8787.78) 14402.83,8787.87 RN9.4@14402.83,8814.17
  Top Layer w10: v2(14410.52,8230.95) U8.D7@14430.19,8211.27
  L6_SIG2 w5: v3(14402.74,8787.78) 14402.74,8526.48 14423.48,8505.73 14423.48,8243.92 v2(14410.52,8230.95)
TFP401_D9: RN9.6 U2.21 | length 3233
  Top Layer w4.7: RN9.6@14422.52,8847.83 v3(14422.52,8874) ; v4(16786.36,9389) 16871.7,9389 U2.21@16871.94,9389.24
  L6_SIG2 w5: v3(14422.52,8874) 14422.52,9136.16 14675.36,9389 14737.85,9389 ccw(c14737.85,9398) 14746.85,9398 cw(c14755.85,9398) 14755.85,9407 14757.85,9407 cw(c14757.85,9398) 14766.85,9398 ccw(c14775.85,9398) 14775.85,9389 14777.85,9389 ccw(c14777.85,9398) 14786.85,9398 cw(c14795.85,9398) 14795.85,9407 14797.85,9407 cw(c14797.85,9398) 14806.85,9398 ccw(c14815.85,9398) 14815.85,9389 14817.85,9389 ccw(c14817.85,9398) 14826.85,9398 cw(c14835.85,9398) 14835.85,9407 14837.85,9407 cw(c14837.85,9398) 14846.85,9398 ccw(c14855.85,9398) 14855.85,9389 14857.85,9389 ccw(c14857.85,9398) 14866.85,9398 cw(c14875.85,9398) 14875.85,9407 14877.85,9407 cw(c14877.85,9398) 14886.85,9398 ccw(c14895.85,9398) 14895.85,9389 14897.85,9389 ccw(c14897.85,9398) 14906.85,9398 cw(c14915.85,9398) 14915.85,9407 14917.85,9407 cw(c14917.85,9398) 14926.85,9398 ccw(c14935.85,9398) 14935.85,9389 14937.85,9389 ccw(c14937.85,9398) 14946.85,9398 cw(c14955.85,9398) 14955.85,9407 14957.85,9407 cw(c14957.85,9398) 14966.85,9398 ccw(c14975.85,9398) 14975.85,9389 14977.85,9389 ccw(c14977.85,9398) 14986.85,9398 cw(c14995.85,9398) 14995.85,9407 14997.85,9407 cw(c14997.85,9398) 15006.85,9398 ccw(c15015.85,9398) 15015.85,9389 15017.85,9389 ccw(c15017.85,9398) 15026.85,9398 cw(c15035.85,9398) 15035.85,9407 15037.85,9407 cw(c15037.85,9398) 15046.85,9398 ccw(c15055.85,9398) 15055.85,9389 15057.85,9389 ccw(c15057.85,9398) 15066.85,9398 cw(c15075.85,9398) 15075.85,9407 15077.85,9407 cw(c15077.85,9398) 15086.85,9398 ccw(c15095.85,9398) 15095.85,9389 15097.85,9389 ccw(c15097.85,9398) 15106.85,9398 cw(c15115.85,9398) 15115.85,9407 15117.85,9407 cw(c15117.85,9398) 15126.85,9398 ccw(c15135.85,9398) 15135.85,9389 15137.85,9389 ccw(c15137.85,9398) 15146.85,9398 cw(c15155.85,9398) 15155.85,9407 15157.85,9407 cw(c15157.85,9398) 15166.85,9398 ccw(c15175.85,9398) 15175.85,9389 15177.85,9389 ccw(c15177.85,9398) 15186.85,9398 cw(c15195.85,9398) 15195.85,9407 15197.85,9407 cw(c15197.85,9398) 15206.85,9398 ccw(c15215.85,9398) 15215.85,9389 15217.85,9389 ccw(c15217.85,9398) 15226.85,9398 cw(c15235.85,9398) 15235.85,9407 15237.85,9407 cw(c15237.85,9398) 15246.85,9398 ccw(c15255.85,9398) 15255.85,9389 15257.85,9389 ccw(c15257.85,9398) 15266.85,9398 cw(c15275.85,9398) 15275.85,9407 15277.85,9407 cw(c15277.85,9398) 15286.85,9398 ccw(c15295.85,9398) 15295.85,9389 15297.85,9389 ccw(c15297.85,9398) 15306.85,9398 cw(c15315.85,9398) 15315.85,9407 15317.85,9407 cw(c15317.85,9398) 15326.85,9398 ccw(c15335.85,9398) 15335.85,9389 15337.85,9389 ccw(c15337.85,9398) 15346.85,9398 cw(c15355.85,9398) 15355.85,9407 15357.85,9407 cw(c15357.85,9398) 15366.85,9398 ccw(c15375.85,9398) 15375.85,9389 15377.85,9389 ccw(c15377.85,9398) 15386.85,9398 cw(c15395.85,9398) 15395.85,9407 15397.85,9407 cw(c15397.85,9398) 15406.85,9398 ccw(c15415.85,9398) 15415.85,9389 15417.85,9389 ccw(c15417.85,9398) 15426.85,9398 cw(c15435.85,9398) 15435.85,9407 15437.85,9407 cw(c15437.85,9398) 15446.85,9398 ccw(c15455.85,9398) 15455.85,9389 15457.85,9389 ccw(c15457.85,9398) 15466.85,9398 cw(c15475.85,9398) 15475.85,9407 15477.85,9407 cw(c15477.85,9398) 15486.85,9398 ccw(c15495.85,9398) 15495.85,9389 v4(16786.36,9389)
TFP401_D9_FPGA: RN9.3 U8.D8 | length 622.4
  Top Layer w4.7: RN9.3@14422.52,8814.17 14422.52,8771.21 v3(14423.27,8770.46)
  Top Layer w10: v2(14449.89,8230.95) U8.D8@14469.56,8211.27
  L6_SIG2 w5: v3(14423.27,8770.46) 14423.27,8537.35 14436.84,8523.78 14436.84,8244 v2(14449.89,8230.95)
TFP401_D10: RN9.7 U2.22 | length 3384.1
  Top Layer w4.7: RN9.7@14442.2,8847.83 v3(14442.2,8891) ; v4(16764.36,9369) 16864.44,9369 U2.22@16865.27,9368.17
  L6_SIG2 w5: v3(14442.2,8891) 14442.2,9093.84 14456.4,9108.04 ccw(c14449.32,9115.11) 14456.4,9122.18 14451.04,9127.54 cw(c14458.11,9134.61) 14465.18,9141.68 14470.54,9136.32 ccw(c14477.61,9143.39) 14484.68,9150.46 14479.32,9155.82 cw(c14486.39,9162.89) 14493.46,9169.96 14498.82,9164.61 ccw(c14505.89,9171.68) 14512.96,9178.75 14507.61,9184.11 cw(c14514.68,9191.18) 14521.75,9198.25 14527.11,9192.89 ccw(c14534.18,9199.96) 14541.25,9207.03 14535.89,9212.39 cw(c14542.96,9219.46) 14550.03,9226.53 14555.39,9221.18 ccw(c14562.46,9228.25) 14569.53,9235.32 14564.17,9240.68 cw(c14571.25,9247.75) 14578.32,9254.82 14583.67,9249.46 ccw(c14590.75,9256.53) 14597.82,9263.6 14592.46,9268.96 cw(c14599.53,9276.03) 14606.6,9283.1 14611.96,9277.74 ccw(c14619.03,9284.81) 14626.1,9291.89 14620.74,9297.24 cw(c14627.81,9304.31) 14634.89,9311.39 14640.24,9306.03 ccw(c14647.31,9313.1) 14654.39,9320.17 14649.03,9325.53 cw(c14656.1,9332.6) 14663.17,9339.67 14668.53,9334.31 ccw(c14675.6,9341.38) 14682.67,9334.31 14717.36,9369 15787.52,9369 cw(c15787.52,9359) 15797.52,9359 ccw(c15807.52,9359) 15817.52,9359 cw(c15827.52,9359) 15837.52,9359 ccw(c15847.52,9359) 15857.52,9359 cw(c15867.52,9359) 15877.52,9359 ccw(c15887.52,9359) 15897.52,9359 cw(c15907.52,9359) 15917.52,9359 ccw(c15927.52,9359) 15937.52,9359 cw(c15947.52,9359) 15957.52,9359 ccw(c15967.52,9359) 15977.52,9359 cw(c15987.52,9359) 15997.52,9359 ccw(c16007.52,9359) 16017.52,9359 cw(c16027.52,9359) 16037.52,9359 ccw(c16047.52,9359) 16057.52,9359 cw(c16067.52,9359) 16077.52,9359 ccw(c16087.52,9359) 16097.52,9359 cw(c16107.52,9359) 16117.52,9359 ccw(c16127.52,9359) 16137.52,9359 cw(c16147.52,9359) 16157.52,9359 ccw(c16167.52,9359) 16177.52,9359 cw(c16187.52,9359) 16197.52,9359 ccw(c16207.52,9359) 16217.52,9359 cw(c16227.52,9359) 16237.52,9359 ccw(c16247.52,9359) 16257.52,9359 cw(c16267.52,9359) 16277.52,9359 ccw(c16287.52,9359) 16297.52,9359 cw(c16307.52,9359) 16307.52,9369 v4(16764.36,9369)
TFP401_D10_FPGA: RN9.2 U8.A8 | length 496.2
  Top Layer w4.7: v3(14442.1,8789.94) 14442.2,8790.04 RN9.2@14442.2,8814.17
  Top Layer w10: v2(14449.89,8349.07) U8.A8@14469.56,8329.4
  L6_SIG2 w5: v3(14442.1,8789.94) 14442.1,8546.91 14449.89,8539.13 v2(14449.89,8349.07)
TFP401_D11: RN9.8 U2.23 | length 3310.5
  Top Layer w4.7: RN9.8@14461.89,8847.83 v3(14461.89,8874) ; v4(16788.36,9350) U2.23@16875.25,9350
  L6_SIG2 w5: v3(14461.89,8874) 14461.89,8891.48 cw(c14471.89,8891.48) 14471.89,8901.48 14474.36,8901.48 ccw(c14474.36,8911.48) 14474.36,8921.48 14471.89,8921.48 cw(c14471.89,8931.48) 14471.89,8941.48 14474.36,8941.48 ccw(c14474.36,8951.48) 14474.36,8961.48 14471.89,8961.48 cw(c14471.89,8971.48) 14471.89,8981.48 14474.36,8981.48 ccw(c14474.36,8991.48) 14474.36,9001.48 14471.89,9001.48 cw(c14471.89,9011.48) 14471.89,9021.48 14474.36,9021.48 ccw(c14474.36,9031.48) 14474.36,9041.48 14471.89,9041.48 cw(c14471.89,9051.48) 14461.89,9051.48 14461.89,9071.53 14723.36,9333 14757.21,9333 ccw(c14757.21,9343) 14767.21,9343 14767.21,9344 cw(c14777.21,9344) 14787.21,9344 14787.21,9343 ccw(c14797.21,9343) 14807.21,9343 14807.21,9344 cw(c14817.21,9344) 14827.21,9344 14827.21,9343 ccw(c14837.21,9343) 14847.21,9343 14847.21,9344 cw(c14857.21,9344) 14867.21,9344 14867.21,9343 ccw(c14877.21,9343) 14887.21,9343 14887.21,9344 cw(c14897.21,9344) 14907.21,9344 14907.21,9343 ccw(c14917.21,9343) 14927.21,9343 14927.21,9344 cw(c14937.21,9344) 14947.21,9344 14947.21,9343 ccw(c14957.21,9343) 14967.21,9343 14967.21,9344 cw(c14977.21,9344) 14987.21,9344 14987.21,9343 ccw(c14997.21,9343) 15007.21,9343 15007.21,9344 cw(c15017.21,9344) 15027.21,9344 15027.21,9343 ccw(c15037.21,9343) 15047.21,9343 15047.21,9344 cw(c15057.21,9344) 15067.21,9344 15067.21,9343 ccw(c15077.21,9343) 15087.21,9343 15087.21,9344 cw(c15097.21,9344) 15107.21,9344 15107.21,9343 ccw(c15117.21,9343) 15127.21,9343 15127.21,9344 cw(c15137.21,9344) 15147.21,9344 15147.21,9343 ccw(c15157.21,9343) 15167.21,9343 15167.21,9344 cw(c15177.21,9344) 15187.21,9344 15187.21,9343 ccw(c15197.21,9343) 15207.21,9343 15207.21,9344 cw(c15217.21,9344) 15227.21,9344 15227.21,9343 ccw(c15237.21,9343) 15247.21,9343 15247.21,9344 cw(c15257.21,9344) 15267.21,9344 15267.21,9343 ccw(c15277.21,9343) 15287.21,9343 15287.21,9344 cw(c15297.21,9344) 15307.21,9344 15307.21,9343 ccw(c15317.21,9343) 15327.21,9343 15327.21,9344 cw(c15337.21,9344) 15347.21,9344 15347.21,9343 ccw(c15357.21,9343) 15367.21,9343 15367.21,9344 cw(c15377.21,9344) 15387.21,9344 15387.21,9343 ccw(c15397.21,9343) 15407.21,9343 15407.21,9344 cw(c15417.21,9344) 15427.21,9344 15427.21,9343 ccw(c15437.21,9343) 15447.21,9343 15447.21,9344 cw(c15457.21,9344) 15467.21,9344 15467.21,9343 ccw(c15477.21,9343) 15477.21,9333 16662.36,9333 16679.36,9350 v4(16788.36,9350)
TFP401_D11_FPGA: RN9.1 U8.B8 | length 540.7
  Top Layer w4.7: RN9.1@14461.89,8814.17 14461.89,8796.47 14466.07,8792.29 v3(14466.07,8771.16)
  Top Layer w10: v2(14449.89,8309.69) U8.B8@14469.56,8290.01
  L6_SIG2 w5: v2(14449.89,8309.69) 14462.74,8322.54 14462.74,8767.83 v3(14466.07,8771.16)
TFP401_D12: RN28.5 U2.24 | length 3223.6
  Top Layer w4.7: RN28.5@14499.37,8848.52 v3(14499.37,8891) ; v4(16765.36,9330) 16765.64,9330.28 U2.24@16881.64,9330.28
  L6_SIG2 w5: v3(14499.37,8891) 14499.37,9063.02 14510.44,9074.08 ccw(c14503.37,9081.15) 14510.44,9088.22 14510.08,9088.58 cw(c14517.15,9095.65) 14524.22,9102.72 14524.58,9102.37 ccw(c14531.65,9109.44) 14538.72,9116.51 14538.37,9116.87 cw(c14545.44,9123.94) 14552.51,9131.01 14552.87,9130.65 ccw(c14559.94,9137.72) 14567.01,9144.79 14566.65,9145.15 cw(c14573.72,9152.22) 14580.79,9159.29 14581.15,9158.94 ccw(c14588.22,9166.01) 14595.29,9173.08 14594.93,9173.44 cw(c14602.01,9180.51) 14609.08,9187.58 14609.43,9187.22 ccw(c14616.51,9194.29) 14623.58,9201.36 14623.22,9201.72 cw(c14630.29,9208.79) 14637.36,9215.86 14637.72,9215.5 ccw(c14644.79,9222.58) 14651.86,9229.65 14651.5,9230 cw(c14658.57,9237.08) 14665.65,9244.15 14666,9243.79 ccw(c14673.07,9250.86) 14680.15,9257.93 14679.79,9258.29 cw(c14686.86,9265.36) 14693.93,9272.43 14694.29,9272.07 ccw(c14701.36,9279.14) 14708.43,9286.21 14708.07,9286.57 cw(c14715.14,9293.64) 14722.21,9300.71 14722.57,9300.36 ccw(c14729.64,9307.43) 14736.71,9300.36 14742.36,9306 15497.74,9306 ccw(c15497.74,9313.5) 15505.24,9313.5 cw(c15512.74,9313.5) 15512.74,9321 15517.74,9321 cw(c15517.74,9313.5) 15525.24,9313.5 ccw(c15532.74,9313.5) 15532.74,9306 15537.74,9306 ccw(c15537.74,9313.5) 15545.24,9313.5 cw(c15552.74,9313.5) 15552.74,9321 15557.74,9321 cw(c15557.74,9313.5) 15565.24,9313.5 ccw(c15572.74,9313.5) 15572.74,9306 15577.74,9306 ccw(c15577.74,9313.5) 15585.24,9313.5 cw(c15592.74,9313.5) 15592.74,9321 15597.74,9321 cw(c15597.74,9313.5) 15605.24,9313.5 ccw(c15612.74,9313.5) 15612.74,9306 15617.74,9306 ccw(c15617.74,9313.5) 15625.24,9313.5 cw(c15632.74,9313.5) 15632.74,9321 15637.74,9321 cw(c15637.74,9313.5) 15645.24,9313.5 ccw(c15652.74,9313.5) 15652.74,9306 15657.74,9306 ccw(c15657.74,9313.5) 15665.24,9313.5 cw(c15672.74,9313.5) 15672.74,9321 15677.74,9321 cw(c15677.74,9313.5) 15685.24,9313.5 ccw(c15692.74,9313.5) 15692.74,9306 15697.74,9306 ccw(c15697.74,9313.5) 15705.24,9313.5 cw(c15712.74,9313.5) 15712.74,9321 15717.74,9321 cw(c15717.74,9313.5) 15725.24,9313.5 ccw(c15732.74,9313.5) 15732.74,9306 15737.74,9306 ccw(c15737.74,9313.5) 15745.24,9313.5 cw(c15752.74,9313.5) 15752.74,9321 15757.74,9321 cw(c15757.74,9313.5) 15765.24,9313.5 ccw(c15772.74,9313.5) 15772.74,9306 15777.74,9306 ccw(c15777.74,9313.5) 15785.24,9313.5 cw(c15792.74,9313.5) 15792.74,9321 15797.74,9321 cw(c15797.74,9313.5) 15805.24,9313.5 ccw(c15812.74,9313.5) 15812.74,9306 15817.74,9306 ccw(c15817.74,9313.5) 15825.24,9313.5 cw(c15832.74,9313.5) 15832.74,9321 15837.74,9321 cw(c15837.74,9313.5) 15845.24,9313.5 ccw(c15852.74,9313.5) 15852.74,9306 15857.74,9306 ccw(c15857.74,9313.5) 15865.24,9313.5 cw(c15872.74,9313.5) 15872.74,9321 15877.74,9321 cw(c15877.74,9313.5) 15885.24,9313.5 ccw(c15892.74,9313.5) 15892.74,9306 15897.74,9306 ccw(c15897.74,9313.5) 15905.24,9313.5 cw(c15912.74,9313.5) 15912.74,9321 15917.74,9321 cw(c15917.74,9313.5) 15925.24,9313.5 ccw(c15932.74,9313.5) 15932.74,9306 15937.74,9306 ccw(c15937.74,9313.5) 15945.24,9313.5 cw(c15952.74,9313.5) 15952.74,9321 15957.74,9321 cw(c15957.74,9313.5) 15965.24,9313.5 ccw(c15972.74,9313.5) 15972.74,9306 15977.74,9306 ccw(c15977.74,9313.5) 15985.24,9313.5 cw(c15992.74,9313.5) 15992.74,9321 15997.74,9321 cw(c15997.74,9313.5) 16005.24,9313.5 ccw(c16012.74,9313.5) 16012.74,9306 16017.74,9306 ccw(c16017.74,9313.5) 16025.24,9313.5 cw(c16032.74,9313.5) 16032.74,9321 16037.74,9321 cw(c16037.74,9313.5) 16045.24,9313.5 ccw(c16052.74,9313.5) 16052.74,9306 16057.74,9306 ccw(c16057.74,9313.5) 16065.24,9313.5 cw(c16072.74,9313.5) 16072.74,9321 16077.74,9321 cw(c16077.74,9313.5) 16085.24,9313.5 ccw(c16092.74,9313.5) 16092.74,9306 16097.74,9306 ccw(c16097.74,9313.5) 16105.24,9313.5 cw(c16112.74,9313.5) 16112.74,9321 16117.74,9321 cw(c16117.74,9313.5) 16125.24,9313.5 ccw(c16132.74,9313.5) 16132.74,9306 16137.74,9306 ccw(c16137.74,9313.5) 16145.24,9313.5 cw(c16152.74,9313.5) 16152.74,9321 16157.74,9321 cw(c16157.74,9313.5) 16165.24,9313.5 ccw(c16172.74,9313.5) 16172.74,9306 16177.74,9306 ccw(c16177.74,9313.5) 16185.24,9313.5 cw(c16192.74,9313.5) 16192.74,9321 16197.74,9321 cw(c16197.74,9313.5) 16205.24,9313.5 ccw(c16212.74,9313.5) 16212.74,9306 16217.74,9306 ccw(c16217.74,9313.5) 16225.24,9313.5 cw(c16232.74,9313.5) 16232.74,9321 16237.74,9321 cw(c16237.74,9313.5) 16245.24,9313.5 ccw(c16252.74,9313.5) 16252.74,9306 16741.36,9306 v4(16765.36,9330)
TFP401_D12_FPGA: RN28.4 U8.C8 | length 592.9
  Top Layer w4.7: v3(14499.24,8789.37) 14499.37,8789.5 RN28.4@14499.37,8814.86
  Top Layer w10: v2(14449.89,8270.32) U8.C8@14469.56,8250.65
  L6_SIG2 w5: v2(14449.89,8270.32) 14474.83,8295.26 14474.83,8729.73 14499.24,8754.14 v3(14499.24,8789.37)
